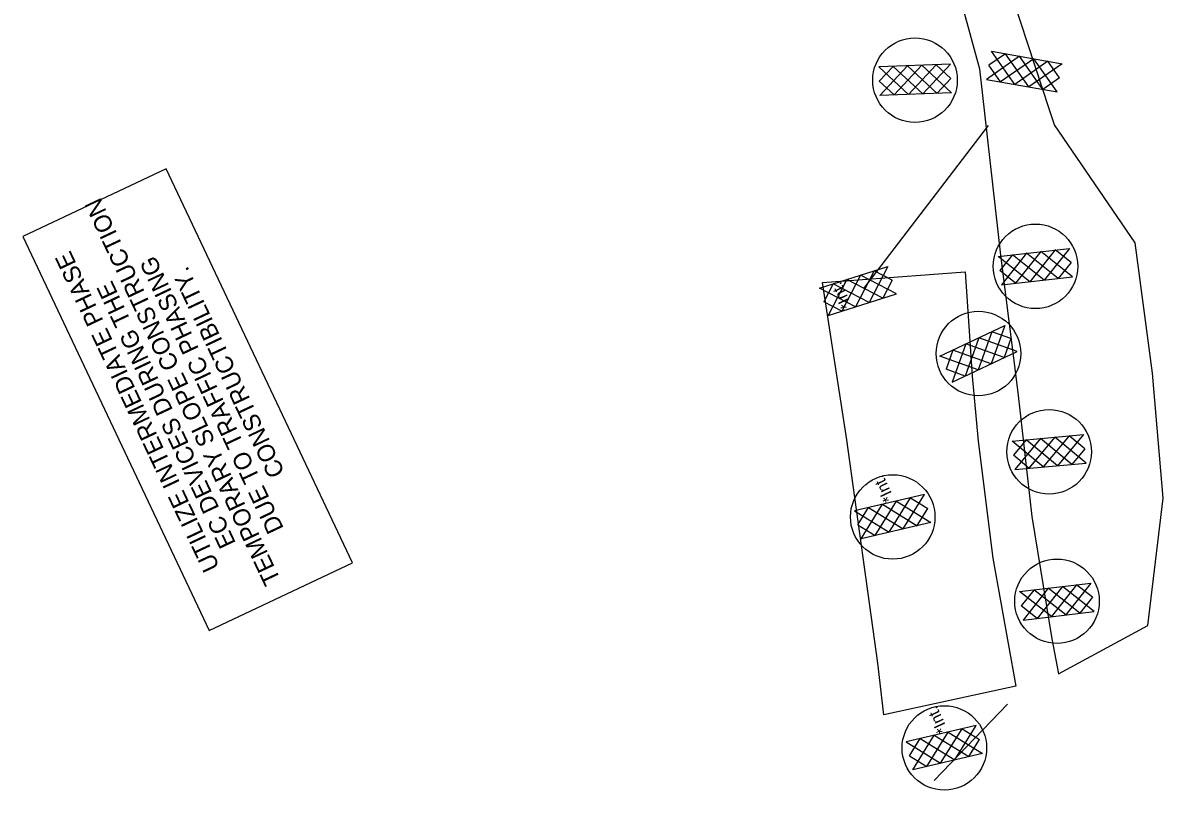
# Model space of a CAD drawing. Extents: x 400935 to 481562, y 415700 to 505362.
# Drawn here: x 477565 to 478024.7, y 498746.8 to 499056.2 of the extents above; entities that cross this region are included whole.
import ezdxf

# ---------------------------------------------------------------- set-up
doc = ezdxf.new("R2010")
doc.units = 0
for name, color, linetype in [('Matting on Slope Note Final CELL', 7, 'Continuous'), ('Old_Level_2', 7, 'Continuous'), ('Rock Silt Check Type A Final CELL', 7, 'Continuous'), ('Rock Silt Check Type A with Matting and PAM Both CELL', 7, 'Continuous'), ('Rock Silt Check Type A with Matting and PAM CG CELL', 7, 'Continuous'), ('Rock Silt Check Type A with Matting and PAM Final CELL', 7, 'Continuous'), ('Scratch_Level_4', 7, 'Continuous')]:
    doc.layers.add(name, color=color, linetype=linetype)

msp = doc.modelspace()

# ---------------------------------------------------------------- linework, layer by layer
at = {"layer": 'Matting on Slope Note Final CELL'}
for p, q in [((477980.89, 499015.16), (477978.88, 499021.21)), ((478013.47, 498967.46), (477980.89, 499015.16)), ((478020.46, 498914.94), (478013.47, 498967.46)), ((478024.74, 498864.51), (478020.46, 498914.94)), ((478018.5, 498813.16), (478024.74, 498864.51)), ((477982.51, 498793.73), (478018.5, 498813.16))]:
    msp.add_line(p, q, dxfattribs=at)
for points in [[(477978.88, 499021.21), (477964.36, 499065.56), (477943.73, 499063.24), (477950.63, 499037.67)], [(477950.63, 499037.67), (477959.16, 498962.55), (477966.16, 498907.15), (477971.74, 498857.14), (477979.79, 498807.77), (477982.51, 498793.73)]]:
    msp.add_lwpolyline(points, dxfattribs=at)
at = {"layer": 'Old_Level_2'}
for p, q in [((477886.19, 498949.24), (477913.75, 498957.94)), ((477908.21, 498956.21), (477900.68, 498941.7)), ((477913.75, 498957.94), (477906.21, 498943.45)), ((477915.49, 498952.46), (477908.21, 498956.21)), ((477897.2, 498952.72), (477889.67, 498938.22)), ((477902.73, 498954.46), (477895.15, 498939.96)), ((477911.7, 498945.18), (477897.2, 498952.72)), ((477917.23, 498946.93), (477902.73, 498954.46)), ((477915.49, 498952.46), (477911.7, 498945.18)), ((477900.68, 498941.7), (477886.19, 498949.24)), ((477891.64, 498950.91), (477887.91, 498943.75)), ((477889.67, 498938.22), (477917.23, 498946.93)), ((477906.21, 498943.45), (477891.67, 498950.97)), ((477895.15, 498939.96), (477887.91, 498943.75)), ((477928.47, 498866), (477900.32, 498859.43)), ((477914.2, 498850.81), (477922.87, 498864.69)), ((477919.84, 498852.13), (477928.47, 498866)), ((477922.87, 498864.69), (477929.8, 498860.35)), ((477900.32, 498859.43), (477914.2, 498850.81)), ((477901.63, 498853.78), (477905.97, 498860.75)), ((477902.95, 498848.18), (477911.57, 498862.06)), ((477905.97, 498860.75), (477919.84, 498852.13)), ((477908.6, 498849.49), (477917.22, 498863.37)), ((477911.57, 498862.06), (477925.49, 498853.44)), ((477917.22, 498863.37), (477931.09, 498854.75)), ((477925.53, 498853.5), (477929.8, 498860.35)), ((477901.63, 498853.78), (477908.6, 498849.49)), ((477931.09, 498854.75), (477902.95, 498848.18)), ((477949.29, 498772.85), (477921.15, 498766.28)), ((477940.67, 498758.98), (477949.29, 498772.85)), ((477922.46, 498760.63), (477926.8, 498767.6)), ((477923.78, 498755.03), (477932.4, 498768.91)), ((477926.8, 498767.6), (477940.67, 498758.98)), ((477929.43, 498756.34), (477938.05, 498770.23)), ((477932.4, 498768.91), (477946.32, 498760.3)), ((477935.02, 498757.66), (477943.69, 498771.54)), ((477938.05, 498770.23), (477951.92, 498761.6)), ((477943.69, 498771.54), (477950.62, 498767.21)), ((477921.15, 498766.28), (477935.02, 498757.66)), ((477946.36, 498760.36), (477950.62, 498767.21)), ((477922.46, 498760.63), (477929.43, 498756.34)), ((477951.92, 498761.6), (477923.78, 498755.03))]:
    msp.add_line(p, q, dxfattribs=at)
msp.add_lwpolyline([(477697.85, 498838.51), (477622.77, 498997.4), (477564.98, 498970.09), (477640.06, 498811.2)], close=True, dxfattribs=at)
for centre in [(477915.7, 498856.96), (477936.52, 498763.81)]:
    msp.add_circle(centre, 17.04, dxfattribs=at)
at = {"layer": 'Rock Silt Check Type A Final CELL'}
for p, q in [((477961.1, 499043.71), (477954.49, 499039.09)), ((477955.5, 499044.75), (477983.96, 499039.75)), ((477964.88, 499031.38), (477955.5, 499044.75)), ((477970.59, 499030.37), (477961.16, 499043.75)), ((477966.87, 499042.75), (477953.5, 499033.37)), ((477959.16, 499032.38), (477954.49, 499039.09)), ((477972.59, 499041.75), (477959.16, 499032.38)), ((477978.25, 499040.77), (477964.88, 499031.38)), ((477976.25, 499029.38), (477966.87, 499042.75)), ((477983.96, 499039.75), (477970.59, 499030.37)), ((477981.97, 499028.38), (477972.59, 499041.75)), ((477982.98, 499034.09), (477978.25, 499040.77)), ((477982.98, 499034.09), (477976.25, 499029.38)), ((477953.5, 499033.37), (477981.97, 499028.38))]:
    msp.add_line(p, q, dxfattribs=at)
at = {"layer": 'Rock Silt Check Type A with Matting and PAM Both CELL'}
for p, q in [((477966.87, 498826.85), (477995.56, 498830.27)), ((477972.53, 498827.48), (477967.53, 498821.14)), ((477978.34, 498828.22), (477968.23, 498815.39)), ((477985.46, 498817.44), (477972.58, 498827.53)), ((477984.09, 498828.91), (477973.94, 498816.07)), ((477991.17, 498818.12), (477978.34, 498828.22)), ((477989.8, 498829.6), (477979.7, 498816.75)), ((477996.93, 498818.8), (477984.09, 498828.91)), ((477995.56, 498830.27), (477985.46, 498817.44)), ((477996.26, 498824.56), (477989.8, 498829.6)), ((477979.7, 498816.75), (477966.87, 498826.85)), ((477996.26, 498824.56), (477991.17, 498818.12)), ((477973.94, 498816.07), (477967.53, 498821.14)), ((477968.23, 498815.39), (477996.93, 498818.8))]:
    msp.add_line(p, q, dxfattribs=at)
msp.add_circle((477981.93, 498822.96), 17.04, dxfattribs=at)
at = {"layer": 'Rock Silt Check Type A with Matting and PAM CG CELL'}
for p, q in [((477938.93, 499039.53), (477910.05, 499038.47)), ((477910.48, 499026.93), (477921.59, 499038.89)), ((477916.27, 499027.13), (477927.39, 499039.11)), ((477921.59, 499038.89), (477933.61, 499027.78)), ((477922.02, 499027.35), (477933.19, 499039.32)), ((477927.39, 499039.11), (477939.36, 499027.99)), ((477927.82, 499027.57), (477938.93, 499039.53)), ((477933.19, 499039.32), (477939.16, 499033.74)), ((477910.05, 499038.47), (477922.02, 499027.35)), ((477910.25, 499032.67), (477915.85, 499038.68)), ((477915.85, 499038.68), (477927.82, 499027.57)), ((477910.25, 499032.67), (477916.27, 499027.13)), ((477933.66, 499027.83), (477939.16, 499033.74)), ((477939.36, 499027.99), (477910.48, 499026.93)), ((477934.74, 498921.77), (477960.87, 498934.12)), ((477960.87, 498934.12), (477955.36, 498918.74)), ((477950.43, 498929.18), (477944.87, 498913.79)), ((477955.62, 498931.65), (477950.12, 498916.26)), ((477965.81, 498923.68), (477950.43, 498929.18)), ((477963.34, 498928.93), (477955.62, 498931.65)), ((477963.34, 498928.93), (477960.56, 498921.2)), ((477939.92, 498924.16), (477937.19, 498916.57)), ((477945.18, 498926.71), (477939.68, 498911.33)), ((477955.36, 498918.74), (477939.94, 498924.23)), ((477960.56, 498921.2), (477945.18, 498926.71)), ((477950.12, 498916.26), (477934.74, 498921.77)), ((477939.68, 498911.33), (477965.81, 498923.68)), ((477944.87, 498913.79), (477937.19, 498916.57))]:
    msp.add_line(p, q, dxfattribs=at)
for centre in [(477924.67, 499033.1), (477950.26, 498922.86)]:
    msp.add_circle(centre, 17.04, dxfattribs=at)
at = {"layer": 'Rock Silt Check Type A with Matting and PAM Final CELL'}
for p, q in [((477958.21, 498962.01), (477986.92, 498965.27)), ((477986.92, 498965.27), (477976.75, 498952.49)), ((477970.99, 498951.84), (477958.21, 498962.01)), ((477963.88, 498962.6), (477958.84, 498956.29)), ((477969.68, 498963.31), (477959.51, 498950.53)), ((477976.75, 498952.49), (477963.92, 498962.66)), ((477975.45, 498963.97), (477965.23, 498951.18)), ((477982.46, 498953.14), (477969.68, 498963.31)), ((477981.16, 498964.63), (477970.99, 498951.84)), ((477988.23, 498953.8), (477975.45, 498963.97)), ((477987.58, 498959.56), (477981.16, 498964.63)), ((477965.23, 498951.18), (477958.84, 498956.29)), ((477987.58, 498959.56), (477982.46, 498953.14)), ((477959.51, 498950.53), (477988.23, 498953.8)), ((477963.82, 498887.57), (477992.6, 498890.17)), ((477976.37, 498877.11), (477963.82, 498887.57)), ((477969.5, 498888.03), (477964.33, 498881.84)), ((477975.32, 498888.61), (477964.86, 498876.06)), ((477982.14, 498877.63), (477969.55, 498888.08)), ((477981.1, 498889.13), (477970.59, 498876.58)), ((477987.87, 498878.15), (477975.32, 498888.61)), ((477986.82, 498889.66), (477976.37, 498877.11)), ((477993.64, 498878.67), (477981.1, 498889.13)), ((477992.6, 498890.17), (477982.14, 498877.63)), ((477993.13, 498884.45), (477986.82, 498889.66)), ((477993.13, 498884.45), (477987.87, 498878.15)), ((477970.59, 498876.58), (477964.33, 498881.84)), ((477964.86, 498876.06), (477993.64, 498878.67))]:
    msp.add_line(p, q, dxfattribs=at)
for centre in [(477973.25, 498958.03), (477978.76, 498883.25)]:
    msp.add_circle(centre, 17.04, dxfattribs=at)
at = {"layer": 'Scratch_Level_4'}
for p, q in [((477904.01, 498949.12), (477954.35, 499014.76)), ((477932.46, 498750.71), (477962.01, 498781.52))]:
    msp.add_line(p, q, dxfattribs=at)
msp.add_lwpolyline([(477965.36, 498788.72), (477912.1, 498777.21), (477909.72, 498798.02), (477897.19, 498888.08), (477887.36, 498951.53), (477944.87, 498955.85), (477946.35, 498933.95), (477947.7, 498913.76), (477950.08, 498887.55), (477956.12, 498840.29)], close=True, dxfattribs=at)

# ---------------------------------------------------------------- texts
at = {"layer": 'Old_Level_2'}
for s, height, rotation, p in [('TEMPORARY SLOPE CONSTRUCTION', 7, 115.2933, (477669.12, 498831.49)), ('UTILIZE INTERMEDIATE PHASE', 7, 115.2933, (477644.48, 498836.81)), ('DUE TO TRAFFIC PHASING', 7, 115.2933, (477670.33, 498852.32)), ('CONSTRUCTIBILITY.', 7, 115.2933, (477670.75, 498874.83)), ('EC DEVICES DURING THE ', 7, 115.2933, (477651.01, 498846.4)), ('*Int.', 4.746, 115.2938, (477899.51, 498942.01)), ('*Int.', 4.746, 115.2938, (477916.49, 498864.22)), ('*Int.', 4.746, 115.2938, (477938.17, 498770.92))]:
    msp.add_text(s, height=height, rotation=rotation, dxfattribs=at).set_placement(p)

doc.saveas('drawing.dxf')
